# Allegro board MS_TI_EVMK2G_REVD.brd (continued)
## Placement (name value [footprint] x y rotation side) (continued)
C628  0.1uF  [CAP0201]  174.02 116.19 135 bottom
C630  0.1uF  [CAP0402]  193.04 96.53 0 bottom
C631  0.1uF  [CAP0201]  177.32 113.71 315 bottom
C632  1uF  [CAP0402]  149.73 97.8 180 bottom
C633  0.01uF  [CAP0402]  65.99 54.88 270 bottom
C634  0.1uF  [CAP0402]  193.34 26.86 90 bottom
C635  0.1uF  [CAP0402]  149.86 94.88 0 bottom
C637  0.1uF  [CAP0402]  142.88 92.6 0 bottom
C638  0.1uF  [CAP0402]  78.31 50.56 90 bottom
C639  0.1uF  [CAP0402]  140.46 97.42 270 bottom
C641  0.1uF  [CAP0402]  146.56 96.66 180 bottom
C642  0.1uF  [CAP0402]  140.59 88.66 0 bottom
C643  0.1uF  [CAP0402]  146.43 88.41 270 bottom
C645  0.1uF  [CAP0402]  194.26 149.52 0 bottom
C646  0.1uF  [CAP0402]  139.7 85.61 90 bottom
C647  0.1uF  [CAP0402]  144.53 85.99 180 bottom
C648  1uF  [CAP0402]  170.59 87.09 90 bottom
C649  0.01uF  [CAP0402]  172.95 89.35 180 bottom
C650  0.01uF  [CAP0402]  169.42 89.4 180 bottom
C651  0.01uF  [CAP0402]  285.33 57.56 180 bottom
C652  0.01uF  [CAP0201]  292.01 54.35 90 bottom
C653  0.01uF  [CAP0402]  173.48 87.77 180 bottom
C654  0.01uF  [CAP0402]  167.89 87.77 0 bottom
C655  0.1uF  [CAP0402]  196.47 79.14 0 bottom
C656  0.1uF  [CAP0402]  202.56 77.74 180 bottom
C657  0.1uF  [CAP0402]  188.98 76.47 90 bottom
C659  1uF  [CAP0402]  196.47 80.66 180 bottom
C661  0.1uF  [CAP0402]  44.32 114.95 270 bottom
C663  0.1uF  [CAP0402]  44.07 110.63 90 bottom
C665  0.1uF  [CAP0402]  100.71 93.99 180 bottom
C666  1uF  [CAP0402]  100.71 92.47 180 bottom
C667  0.1uF  [CAP0402]  117.86 127.4 270 top
C668  0.1uF  [CAP0402]  119.38 127.4 270 top
C669  0.1uF  [CAP0402]  120.9 127.4 270 top
C670  0.1uF  [CAP0402]  108.2 91.07 270 bottom
C671  0.01uF  [CAP0402]  11.94 43.58 270 bottom
C672  0.1uF  [CAP0402]  181.91 45.48 90 bottom
C673  0.01uF  [CAP0402]  181.53 39.89 180 bottom
C674  0.1uF  [CAP0402]  276.61 47.26 90 bottom
C675  0.1uF  [CAP0402]  37.77 129.99 0 bottom
C676  0.1uF  [CAP0402]  114.5 52.49 270 bottom
C677  10uF  [CAP0805]  121.03 109.36 270 top
C678  0.1uF  [CAP0402]  119.25 109.11 270 top
C679  0.1uF  [CAP0402]  281.94 43.96 0 bottom
C680  0.1uF  [CAP0402]  38.28 127.57 90 bottom
C681  0.01uF  [CAP0402]  36.6 203.8 90 top
C683  0.1uF  [CAP0402]  96.85 39.74 0 bottom
C684  0.1uF  [CAP0402]  96.85 36.57 0 bottom
C685  0.1uF  [CAP0402]  169.6 50.43 270 bottom
C686  0.01uF  [CAP0402]  170.26 52.47 0 bottom
C687  0.1uF  [CAP0402]  270.26 36.97 90 bottom
C688  0.1uF  [CAP0402]  38.28 124.53 270 bottom
C689  0.1uF  [CAP0402]  99.57 42.1 270 bottom
C690  0.1uF  [CAP0402]  30.53 123.89 90 bottom
C691  0.1uF  [CAP0402]  271.91 36.97 90 bottom
C692  0.1uF  [CAP0402]  286.38 39 90 bottom
C693  0.1uF  [CAP0402]  101.3 42.15 270 bottom
C694  0.1uF  [CAP0402]  102.31 33.52 90 bottom
C695  0.1uF  [CAP0402]  279.02 36.21 0 bottom
C696  0.1uF  [CAP0402]  275.59 36.21 0 bottom
C697  1uF  [CAP0402]  103.07 51.81 270 bottom
C698  0.1uF  [CAP0402]  103.07 42.15 270 bottom
C699  1uF  [CAP0402]  104.6 51.81 270 bottom
C700  0.1uF  [CAP0402]  105.11 37.2 180 bottom
C701  0.1uF  [CAP0402]  96.6 31.74 180 bottom
C702  10uF  [CAP0805]  275.34 31.89 90 bottom
C703  0.1uF  [CAP0402]  129.62 27.42 90 bottom
C704  0.01uF  [CAP0402]  85.51 28.95 270 bottom
C706  0.01uF  [CAP0402]  91.98 20.06 270 bottom
C707  0.01uF  [CAP0402]  84.87 20.56 90 bottom
C708  0.1uF  [CAP0402]  124.28 18.66 270 bottom
C709  10uF  [CAP0805]  124.66 13.71 90 bottom
C710  0.01uF  [CAP0402]  157.91 150.18 270 top
C711  4.7uF  [CAP0603]  273.43 151.53 0 bottom
C712  0.1uF  [CAP0402]  279.53 151.91 270 bottom
C713  4.7uF  [CAP0603]  256.79 151.02 0 bottom
C714  0.1uF  [CAP0402]  278 151.91 270 bottom
C715  0.1uF  [CAP0402]  262.89 152.03 270 bottom
C716  0.1uF  [CAP0402]  261.37 152.03 270 bottom
C717  4.7uF  [CAP0603]  242.82 150 0 bottom
C718  0.1uF  [CAP0402]  248.67 151.02 270 bottom
C719  0.1uF  [CAP0402]  247.14 151.02 270 bottom
C720  4.7uF  [CAP0603]  243.2 141.24 0 bottom
C721  0.1uF  [CAP0402]  248.79 142.51 270 bottom
C722  0.1uF  [CAP0402]  247.27 142.51 270 bottom
C723  4.7uF  [CAP0603]  255.19 140.78 180 bottom
C724  0.1uF  [CAP0402]  267.97 141.24 270 bottom
C725  0.1uF  [CAP0402]  266.45 141.24 270 bottom
C726  0.1uF  [CAP0402]  116.46 200.17 90 bottom
C733  0.1uF  [CAP0402]  293.73 52.64 180 bottom
C734  0.1uF  [CAP0402]  34.11 61.41 0 bottom
C735  22uF  [CAP0805]  93.85 46.7 270 top
C737  10uF  [CAP1210]  243.99 228.74 0 top
C738  10uF  [CAP1210]  243.99 232.42 0 top
C739  10uF  [CAP1210]  243.99 236.11 0 top
C740  0.1uF  [CAP0402]  243.79 237.33 0 bottom
C741  1uF  [CAP0402]  239.09 241.65 90 top
C742  3300pF  [CAP0805]  237.57 244.95 90 top
C743  0.1uF  [CAP0402]  239.34 233.39 180 top
C744  22uF  [CAP1210]  229.95 233.75 0 top
C745  22uF  [CAP1210]  229.95 233.75 0 bottom
C746  0.1uF  [CAP0402]  230.07 236.54 0 bottom
C749  0.1uF  [CAP0402]  294.31 233.67 180 bottom
C750  10uF  [CAP0805]  294.18 236.34 180 top
C752  3.3uF  [CAP0603]  35.56 186.5 90 bottom
C753  0.1uF  [CAP0402]  37.06 180.05 180 bottom
C754  3.3uF  [CAP0603]  28.91 150.61 90 bottom
C755  0.1uF  [CAP0402]  34.24 141.47 180 bottom
C756  0.01uF  [CAP0402]  126.9 103.06 0 top
C757  0.01uF  [CAP0402]  135 102.1 270 top
C758  1uF  [CAP0402]  134.04 107.03 180 top
C759  0.1uF  [CAP0402]  129.41 106.31 90 top
C760  0.1uF  [CAP0201]  155.93 107.08 270 bottom
C761  0.1uF  [CAP0402]  209.04 181.24 0 bottom
C762  0.1uF  [CAP0402]  193.04 221.93 90 top
C763  0.1uF  [CAP0402]  193.04 210.12 90 top
C775  0.01uF  [CAP0402]  130.73 33.29 0 bottom
C776  0.01uF  [CAP0402]  224.54 246.6 180 bottom
C777  0.1uF  [CAP0402]  157.1 95.14 0 top
C778  1uF  [CAP0402]  157.1 96.66 0 top
C780  0.1uF  [CAP0402]  215.26 89.17 0 top
C781  0.1uF  [CAP0402]  215.26 90.69 0 top
C782  0.1uF  [CAP0402]  232 94.71 0 top
C783  0.1uF  [CAP0402]  231.47 110.81 180 top
C784  0.1uF  [CAP0402]  191.13 141.87 180 top
C785  0.01uF  [CAP0402]  205.06 147.43 0 top
C786  0.01uF  [CAP0402]  208.24 147.43 180 top
C789  0.1uF  [CAP0402]  194.88 152.53 90 bottom
C790  0.01uF  [CAP0402]  208.98 153.08 180 bottom
C791  0.01uF  [CAP0402]  205.8 153.08 180 bottom
C792  0.1uF  [CAP0402]  41.66 107.33 90 top
C793  0.01uF  [CAP0201]  123.44 224.55 180 top
C794  1uF  [CAP0402]  202.95 135.02 0 top
C795  3.3uF  [CAP0402]  202.95 133.36 0 top
C796  4.7uF  [CAP0603]  202.82 133.36 0 bottom
C797  0.33uF  [CAP0201]  202.95 135.02 0 bottom
C798  0.01uF  [CAP0402]  108.84 194.58 90 top
C799  0.01uF  [CAP0402]  100.71 237.63 270 top
C800  0.01uF  [CAP0402]  295.15 66.31 0 top
C801  10uF  [CAP1210]  293.98 197.96 0 top
C802  10uF  [CAP1210]  293.9 194.22 0 top
C803  10uF  [CAP1210]  289.48 192.75 270 top
C804  0.1uF  [CAP0402]  290.17 199.51 90 top
C805  0.1uF  [CAP0402]  285.83 195.04 180 top
C806  15pF  [CAP0402]  287.43 202.96 90 top
C807  22uF  [CAP1210]  276.83 195.54 0 top
C808  22uF  [CAP1210]  271.5 195.57 180 top
C809  0.1uF  [CAP0402]  277.27 198.24 0 top
C810  1uF  [CAP0402]  285.93 204.84 90 top
C811  3300pF  [CAP0805]  281.48 204.43 180 top
C812  0.01uF  [CAP0402]  206.04 212.35 0 top
C813  0.01uF  [CAP0402]  216.99 211.75 270 top
C815  0.01uF  [CAP0402]  161.77 219.34 0 top
C816  0.1uF  [CAP0402]  37.11 208.24 0 top
C817  0.1uF  [CAP0402]  37.11 206.72 0 top
C818  0.1uF  [CAP0402]  44.48 212.69 90 top
C819  0.1uF  [CAP0402]  46 212.69 90 top
C820  0.1uF  [CAP0402]  28.96 92.98 180 top
C821  0.1uF  [CAP0402]  24.64 95.77 90 top
C822  0.1uF  [CAP0402]  28.96 94.5 180 top
C824  0.1uF  [CAP0603]  274.45 212.1 180 bottom
C825  22uF_100V  [CAPAE_GCASE]  270.05 227.8 0 top
C826  0.1uF  [CAP0603]  282.57 215.91 0 bottom
C827  0.01uF  [CAP0402]  279.02 215.91 180 bottom
D2  TLV431ACDBVR  [SOT23-5]  288.52 105.15 270 top
D3  B540C-13-F  [DIO_SMC]  268.22 237.12 180 top
D4  MMSD103T1G  [DIO_SOD123]  164.52 55.39 0 top
D5  B240A-13-F  [DIO_SMA]  136.91 228.11 180 bottom
D6  TPD1E10B06DPY  [DIO_DFN0402]  125.98 237.89 270 top
D7  TPD1E10B06DPY  [DIO_DFN0402]  108.27 238.01 270 top
D8  TPD1E10B06DPY  [DIO_DFN0402]  116.77 238.01 270 top
D9  TPD1E10B06DPY  [DIO_DFN0402]  98.99 238.27 270 top
D10  TPD1E10B06DPY  [DIO_DFN0402]  90.87 238.01 270 top
D11  TPD1E10B06DPY  [DIO_DFN0402]  82.61 238.14 270 top
D12  TPD1E10B06DPY  [DIO_DFN0402]  270.13 170.32 90 top
D13  TPD1E10B06DPY  [DIO_DFN0402]  282.12 170.32 90 top
D14  TPD2EUSB30DRTR  [SOT-3]  194.18 13.86 90 top
D15  TPD2EUSB30DRTR  [SOT-3]  215.77 24.53 90 top
D17  SMCJ64CA  [DIO_SMC]  257.81 236.49 180 top
D18  BZT52C13S  [DIO_SOD323]  249.05 226.2 180 top
D19  S1G-13-F  [DIO_SMA]  248.92 240.93 270 top
F2  5A  [FUSE_1206]  259.66 246.24 270 top
FB1  300E  [IND0603]  263.12 13.05 270 bottom
FB2  120E  [IND0402]  198.63 247.16 0 top
FB3  220E  [IND0603]  256.31 18.18 90 top
FB5  120E  [IND0402]  202.56 227.73 90 top
FB6  220E  [IND0603]  231.39 52.08 90 bottom
FB7  120E  [IND0402]  178.16 217.52 270 top
FB8  120E  [IND0402]  168.33 227.24 270 top
FB9  120E  [IND0402]  168.33 227.24 270 bottom
FB11  10E  [IND_201209_90X60_SMD]  152.15 48.33 90 top
FB13  120E  [IND0402]  265.56 173.88 90 top
FB14  120E  [IND0402]  229.49 85.36 90 top
FB15  120E  [IND0402]  226.44 160.29 90 top
FB17  120E  [IND0402]  174.32 137.53 270 bottom
FB19  120E  [IND0402]  182.07 138.9 270 bottom
FB20  120E  [IND0402]  157.71 139.11 180 bottom
FB21  120E  [IND0402]  182.63 143.96 270 bottom
FB22  120E  [IND0402]  187.25 144.34 270 bottom
FB23  120E  [IND0402]  189.28 126.23 90 bottom
FB24  120E  [IND0402]  189.23 122.75 270 bottom
FB25  120E  [IND0402]  192.2 119.5 180 bottom
FB26  1K  [EMIFIL_BLM15H_0402]  145.67 99.33 0 top
FB27  120E  [IND0402]  167.64 102.25 180 top
FB28  120E  [IND0402]  173.53 102.22 0 bottom
FB29  120E  [IND0402]  170.87 101.84 90 bottom
FB30  120E  [IND0402]  184.02 96.61 90 bottom
FB31  1K  [EMIFIL_BLM15H_0402]  149.73 96.66 0 top
FB32  120E  [IND0402]  76.91 54.11 270 top
FB33  120E  [IND0402]  6.98 68.98 180 top
FB34  120E  [IND0402]  14.12 130.09 90 bottom
FB35  300E  [IND0603]  90.25 44.44 180 top
FB36  10E  [IND_201209_90X60_SMD]  166.37 47.49 0 bottom
FB37  10E  [IND_201209_90X60_SMD]  176.02 45.15 90 bottom
FB38  300E  [IND0603]  110.54 31.23 0 top
FB39  300E  [IND0603]  95.78 46.7 90 top
FB40  10E  [IND_201209_90X60_SMD]  171.65 42.18 180 bottom
FB41  120E  [IND0402]  286.38 34.43 90 top
FB42  120E  [IND0402]  79.5 18.66 270 bottom
FB43  120E  [IND0402]  232.41 20.69 270 bottom
FB44  120E  [IND0402]  206.6 13.3 0 bottom
FB45  120E  [IND0402]  216.97 33.31 180 top
FB46  120E  [IND0402]  188.54 9.67 0 bottom
FB47  120E  [IND0402]  193.65 20.46 270 top
FB48  120E  [IND0402]  118.8 13.68 90 top
FB49  120E  [IND0402]  231.95 31.97 0 top
FB51  120E  [IND0402]  294.31 234.43 0 top
FB52  120E  [IND0402]  294.06 141.96 0 top
FB53  120E  [IND0402]  294.59 243.61 0 top
FL1  120E  [EMIFIL_BLM18R_0603]  249.94 247.66 180 top
FL2  120E  [EMIFIL_BLM18R_0603]  205.49 218.58 0 top
FL3  0.47uF  [EMIFIL_NFM18PS_0603]  253.14 46.34 180 top
FL5  0.47uF  [EMIFIL_NFM18PS_0603]  253.21 42.48 180 top
FL6  120E  [EMIFIL_BLM18R_0603]  293.5 156.86 0 top
FL7  670pF  [EMIFIL_NFL21SP_0805]  117.98 95.62 90 top
FL8  670pF  [EMIFIL_NFL21SP_0805]  99.31 97.42 180 top
FL9  670pF  [EMIFIL_NFL21SP_0805]  113.39 91.35 180 top
FL11  120E  [EMIFIL_BLM18R_0603]  117.02 13.17 90 top
FL13  50E  [EMIFIL_BLM31P_1206]  245.41 35.17 90 top
FL14  50E  [EMIFIL_BLM31P_1206]  259.69 45.28 90 top
FL15  50E  [EMIFIL_BLM31P_1206]  250.42 34.23 90 top
FL16  50E  [EMIFIL_BLM31P_1206]  247.88 34.23 90 top
FL19  120E  [EMIFIL_BLM18K_0603]  202.51 233.36 0 top
J1  CON_MUSB-B_5_F  [CON_USBB5_54819-0511_S_R_T]  256.57 13.86 0 top
J2  CON_EDGE_50X2  [CON_ED50X2_MEC6-150_S_R_S]  177.67 244.49 180 top
J3  CON_PWRJACK3_RAPC722  [CON_PWRJACK3_RAPC722_P_R_T]  282.96 237.15 180 top
J4  HDR_6X1  [HDR_6X1_100_S_T]  254.53 82.59 0 top
J5  CON36_PCI  [CON_PCI_18X2_10061913_S_S_S]  212.72 230.52 270 top
J6  HDR_1X4  [HDR_1X4_100_640454-4_S_T]  15.21 232.86 270 top
J7  HDR_7X2  [HDR_7X2_100_S_T]  104.17 217.97 90 top
J8  CON_10X2  [CON_10X2_FTR-110-51-S-D_P_S_S]  269.11 76.01 0 top
J9  HDR_3X1  [HDR_3X1_100_S_T]  93.09 197.12 90 top
J10  HDR_2X1  [HDR_2X1_100_S_T]  61.85 188.48 270 top
J11  HDR_3X1  [HDR_3X1_100_S_T]  103.38 189.75 0 top
J12  HDR_2X25  [HDR_2X25_100_S_T]  299.95 236.97 270 top
J13  HDR_2X1  [HDR_2X1_100_S_T]  235.71 153.18 0 top
J14  HDR_2X1  [HDR_2X1_100_S_T]  212.04 26.74 0 top
J15  HDR_3X1  [HDR_3X1_100_S_T]  64.36 157.01 0 top
J16  HDR_3X1  [HDR_3X1_100_S_T]  74.88 157.11 0 top
J17  HDR_3X1  [HDR_3X1_100_S_T]  271.02 178.45 0 top
J18  HDR_5X1  [HDR_5X1_100_S_T]  273.94 123.71 0 top
J19  CON_PMC_30X2_F  [CON_PMC30X2_HQCD-030_S_S_S]  217.93 77.61 180 top
J21  CON_FLEX_1X6_68610614122  [CON_FLEX_6X1_68610_S_R_S]  68.53 50.65 0 top
J22  CON_FLEX_1X40_62684-4011  [CON_FLEX40X1_62684-40_S_R_S]  44.39 58.65 180 top
J23  CON_MUSB-B_5_F  [CON_USBAB5_54819-0572_S_R_S]  3.2 61.1 0 top
J25  HDR_2X1  [HDR_2X1_100_S_T]  44.3 162.88 90 top
J26  HDR_2X1  [HDR_2X1_100_S_T]  39.12 198.34 90 top
J27  HDR_2X1  [HDR_2X1_100_S_T]  134.06 29.71 180 top
J28  HDR_2X1  [HDR_2X1_100_S_T]  139.52 29.71 180 top
J29  HDR_2X1  [HDR_2X1_100_S_T]  144.86 29.71 180 top
J30  HDR_2X1  [HDR_2X1_100_S_T]  191.97 16.5 0 top
J31  CON_RJ45-14_LPJG16314A4NL  [CON_RJ45-14_LPJG16314A4NL_S_R_T]  164.01 26.81 0 top
J32  CON_AUDIOJACK4_SJ-3524-SMT  [CON_AV4_SJ-3524-SMT-1_R_S]  275.08 15.51 90 top
J33  CON_AUDIOJACK4_SJ-3524-SMT  [CON_AV4_SJ-3524-SMT-1_R_S]  288.42 15.51 90 top
J34  CON_PMC_20X2_F  [CON_PMC20X2_QSH-D-DP_S_S_S]  131.52 15.86 180 top
J35  CON_USB-A_87583-2010BLF  [CON_USBA4_87583-2010_S_R_S]  215.81 13.95 0 top
J36  CON_HDMI_19X1  [CON_19X1_10029449-001RLF_S_R_S]  86.69 11.72 0 top
J37  CON_SDCARD_8_DM3AT-SF-PEJM5  [CON_SD_8_DM3AT-SF-PEJM_S_R_S]  239.19 15.98 0 top
J38  CON_USB-AB_5_M  [CON_USBAB5_ZX62_P_R_S]  194.48 8.68 0 top
J39  HDR_2X1  [HDR_2X1_100_S_T]  275.21 156.48 0 top
J40  HDR_2X1  [HDR_2X1_100_S_T]  258.19 154.7 0 top
J41  HDR_2X1  [HDR_2X1_100_S_T]  242.57 154.95 0 top
J42  HDR_2X1  [HDR_2X1_100_S_T]  244.98 144.03 0 top
J43  HDR_2X1  [HDR_2X1_100_S_T]  256.54 144.54 0 top
J44  HDR_3X1  [HDR_3X1_100_S_T]  231.14 248.05 90 top
J45  HDR_3X1  [HDR_3X1_100_S_T]  287.91 69.86 90 top
J46  HDR_3X1  [HDR_3X1_100_S_T]  260.99 227.6 0 top
J48  HDR_3X1  [HDR_3X1_100_S_T]  150.95 29.71 180 top
J49  HDR_6X1  [HDR_6X1_100_S_T]  44.55 100.07 0 top
J50  HDR_2X1  [HDR_2X1_100_S_T]  293.62 229.12 0 top
JP1  HDR_2X50  [HDR_2X50_100_S_T]  299.97 143.68 270 top
L1  22uH  [IND_DR1040_415X405_SMD]  141.1 223.92 0 top
L2  2.2uH  [IND1008]  276.83 98.92 90 top
L3  3.3uH  [IND_PCMB104T_455X405_SMD]  254.76 209.44 180 top
L4  2.7uH  [IND_XAL7030_315X315_SMD]  254.25 190.64 0 top
L5  2.2uH  [IND_VLCF5020T_205X210_SMD]  234.06 181.12 0 top
L6  2.2uH  [IND_VLCF5020T_205X210_SMD]  254.76 168.29 270 top
L7  2.2uH  [IND_VLCF5020T_205X210_SMD]  233.81 166.26 180 top
L8  4.7uH  [IND_VLCF5020T_205X210_SMD]  48.97 75.76 180 top
L9  2.2uH  [IND_B82476A_510X370_SMD]  233.53 226.91 180 top
L10  2.2uH  [IND_B82476A_510X370_SMD]  280.31 188.58 180 top
L11  47nH  [FILTRER_COILCRAFT_0805]  197.87 18.43 180 top
L12  47nH  [FILTRER_COILCRAFT_0805]  215.77 27.45 270 top
LD1  598-8140-107F  [LED_0805]  69.75 138.36 90 top
LD2  598-8140-107F  [LED_0805]  77.5 138.36 90 top
LD3  598-8140-107F  [LED_0805]  65.94 138.36 90 top
LD4  598-8140-107F  [LED_0805]  73.69 138.36 90 top
LD5  598-8140-107F  [LED_0805]  80.8 138.36 90 top
LD6  598-8170-107F  [LED_0805]  261.49 22.11 270 top
LD7  598-8170-107F  [LED_0805]  257.56 22.24 270 top
LD8  598-8170-107F  [LED_0805]  253.36 22.37 270 top
LD9  598-8170-107F  [LED_0805]  253.94 246.01 0 top
LD10  598-8170-107F  [LED_0805]  61.75 138.36 90 top
LD11  598-8191-107F  [LED_0805]  24.38 247.16 90 top
LD12  598-8170-107F  [LED_0805]  28.83 247.16 90 top
LD13  598-8191-107F  [LED_0805]  57.68 138.36 90 top
LD14  598-8110-107F  [LED_0805]  253.94 241.19 0 top
LD15  598-8110-107F  [LED_0805]  253.56 243.6 180 top
MOD1  NHD-C12832A1Z-NSW-BBW-3V3  [MOD17_NHD-C12832A1Z]  42.93 224 0 top
NOREF  -  [unnamed]  8.26 17.16 0 top
NOREF#2  -  [#2]  149.92 161.69 0 top
NOREF#3  -  [#2]  94.11 -165.34 0 top
NOREF#4  -  [#2]  140.59 20.72 0 top
NOREF#5  -  [unnamed#3]  5.71 135.78 180 top
NOREF#6  -  [#2]  149.92 166.26 0 top
NOREF#7  -  [#2]  0.64 251.09 0 top
NOREF#8  -  [unnamed#3]  110.87 11.46 0 top
NOREF#9  -  [unnamed]  12.78 33.34 0 top
NOREF#10  -  [unnamed#3]  300.55 245.92 0 top
NOREF#11  -  [#2]  0.64 258 0 top
NOREF#12  -  [unnamed]  8.26 238.14 0 top
NOREF#13  -  [unnamed]  295.27 17.16 0 top
NOREF#14  -  [unnamed#3]  111.6 135.78 0 top
NOREF#15  -  [unnamed]  10.95 254.37 0 top
NOREF#16  -  [#2]  -211.46 -64.95 0 top
NOREF#17  -  [#2]  305.63 0 90 top
NOREF#18  -  [unnamed]  5.82 3.24 0 top
NOREF#19  -  [unnamed#3]  300.55 166.92 180 top
NOREF#20  -  [unnamed#3]  300.55 11.46 0 top
NOREF#21  -  [#2]  40.51 -47.36 0 top
NOREF#22  -  [#2]  305.63 7 90 top
NOREF#23  -  [#2]  41.2 218.1 0 top
NOREF#24  -  [unnamed]  12.78 84.14 0 top
NOREF#25  -  [unnamed]  123.98 84.11 0 top
NOREF#26  -  [unnamed]  10.95 3.37 0 top
NOREF#27  -  [unnamed#3]  5.71 245.92 0 top
NOREF#28  -  [unnamed#3]  134.82 245.92 0 top
NOREF#29  -  [unnamed#3]  261.6 135.78 0 top
NOREF#30  -  [#2]  0.64 6.79 0 top
NOREF#31  -  [unnamed]  296.04 254.37 0 top
NOREF#32  -  [unnamed]  5.82 254.27 0 top
NOREF#33  -  [unnamed#3]  5.71 11.46 0 top
NOREF#34  -  [#2]  -224.16 -63.92 0 top
NOREF#35  -  [unnamed]  123.9 33.34 0 top
NOREF#36  -  [unnamed]  300.1 254.27 0 top
NOREF#37  -  [unnamed#3]  300.55 151.92 180 top
NOREF#38  -  [unnamed#3]  152.17 11.46 0 top
NOREF#39  -  [unnamed]  10.95 254.37 180 bottom
NOREF#40  -  [#2]  117.04 73.14 180 bottom
NOREF#41  -  [unnamed]  296.04 254.37 180 bottom
NOREF#42  -  [unnamed]  295.27 17.16 180 bottom
NOREF#43  -  [unnamed]  8.26 17.16 180 bottom
NOREF#44  -  [unnamed]  10.95 3.37 180 bottom
NOREF#45  -  [unnamed]  8.26 238.14 180 bottom
P1  CON_DSUB_9_M  [CON_DB9_182-009-113R531_P_R_T]  11.68 119.52 270 top
P2  CON_DSUB_9_M  [CON_DB9_182-009-113R531_P_R_T]  11.68 205.32 270 top
P3  CON_DSUB_9_M  [CON_DB9_182-009-113R531_P_R_T]  11.68 162.52 270 top
Q6  BSS138  [TO_SOT23-123]  257.56 26.86 180 top
Q7  BSS138  [TO_SOT23-123]  253.36 26.94 180 top
Q8  BSS138  [TO_SOT23-123]  61.87 133.44 0 top
Q9  BSS138  [TO_SOT23-123]  24.26 242.33 0 top
Q10  BSS138  [TO_SOT23-123]  28.83 242.33 0 top
Q11  BSS138  [TO_SOT23-123]  57.68 133.44 0 top
Q12  BSS138  [TO_SOT23-123]  39.83 81.22 0 top
Q13  FDT434P  [SOT223-3]  156.9 45.99 180 top
Q14  BSS138  [TO_SOT23-123]  69.75 133.7 0 top
Q15  BSS138  [TO_SOT23-123]  65.94 133.7 0 top
Q19  BSS138  [TO_SOT23-123]  249.3 229.63 0 top
Q20  SUM60N10-17-E3  [D2PAK-3]  283.77 226.38 0 top
R1  4.7K_5%  [RES0402]  89.69 116.12 270 top
R2  4.7K_5%  [RES0402]  91.21 116.12 90 bottom
R3  4.7K_5%  [RES0402]  96.79 116.12 270 top
R4  4.7K_5%  [RES0402]  96.79 116.12 90 bottom
R5  10K_1%  [RES0402]  94.62 179.21 180 top
R11  10K_1%  [RES0402]  92.74 116.12 90 top
R12  68E  [RES0402]  69.75 138.46 90 bottom
R13  68E  [RES0402]  65.94 138.33 90 bottom
R14  68E  [RES0402]  80.8 138.5 90 bottom
R15  68E  [RES0402]  73.69 138.5 90 bottom
R16  68E  [RES0402]  77.5 138.5 90 bottom
R17  0E_1%  [RES0402]  149.73 80.53 0 top
R18  0E_1%  [RES0402]  149.73 82.06 0 top
R19  0E_1%  [RES0402]  153.54 83.74 0 top
R20  0E_1%  [RES0402]  153.54 82.18 0 top
R21  0E_1%  [RES0402]  150.37 85.87 0 top
R22  0E_1%  [RES0402]  150.37 84.38 0 top
R23  0E_1%  [RES0402]  150.62 89.3 0 top
R24  0E_1%  [RES0402]  150.62 90.82 0 top
R30  1K  [RES0402]  256.92 247.03 270 top
R31  470E  [RES0402]  259.59 21.81 90 top
R32  470E  [RES0402]  255.52 21.94 90 top
R33  470E  [RES0402]  251.46 22.07 90 top
R34  0E_1%  [RES0402]  264.44 13.48 270 top
R35  V5.5MLA0603H  [VAR0603]  259.87 18.18 270 top
R36  2.2K_1%  [RES0402]  257.51 29.86 180 top
R37  2.2K_1%  [RES0402]  253.36 29.86 180 top
R38  10K_1%  [RES0402]  220.98 237.38 180 top
R39  0E_1%  [RES0402]  60.86 129.5 270 top
R40  10K_1%  [RES0402]  23.37 238.52 90 top
R41  0E_1%  [RES0402]  28.07 238.52 270 top
R42  0E_1%  [RES0402]  56.79 129.63 270 top
R43  10K_1%  [RES0402]  220.98 235.47 180 top
R44  100K  [RES0402]  285.6 91.94 0 top
R45  1K  [RES0402]  250.44 86.5 90 top
R46  2.2K_1%  [RES0402]  248.72 86.45 90 top
R47  2.94K_1%  [RES0402]  284.07 100.95 270 top
R48  0E_1%  [RES0402]  176.66 236.23 270 top
R49  0E_1%  [RES0402]  178.18 236.23 270 top
R50  0E_1%  [RES0402]  179.7 236.23 270 top
R51  0E_1%  [RES0402]  181.23 236.23 270 top
R52  10K_1%  [RES0402]  182.88 236.23 90 top
R53  10K_1%  [RES0402]  184.4 236.23 90 top
R54  10K_1%  [RES0402]  185.93 236.23 90 top
R55  10K_1%  [RES0402]  187.45 236.23 90 top
R56  10K_1%  [RES0402]  188.98 236.23 90 top
R57  10K_1%  [RES0402]  190.5 236.23 90 top
R58  10K_1%  [RES0402]  192.02 236.23 90 top
R59  0E_1%  [RES0402]  195.2 236.23 270 top
R60  0E_1%  [RES0402]  169.04 235.98 270 top
R61  0E_1%  [RES0402]  170.56 235.98 270 top
R62  0E_1%  [RES0402]  172.08 235.98 270 top
R63  0E_1%  [RES0402]  173.61 235.98 270 top
R64  10K_1%  [RES0402]  282.55 100.95 90 top
R65  0E_1%  [RES0402]  219.79 242.36 0 top
R66  10K_1%  [RES0402]  219.79 244.26 0 top
R67  10K_1%  [RES0402]  280.25 100.32 180 top
R68  100K  [RES0402]  280.01 92.06 270 top
R69  0E  [RES0402]  198.25 232.42 180 top
R71  1K_1%  [RES0603]  128.02 230.77 270 top
R72  10K_1%  [RES0402]  259.46 97.3 270 top
R73  30.1K _1%  [RES0402]  198.37 230.39 0 top
R75  10K_1%  [RES0402]  276.45 93.59 0 top
R76  2.94K_1%  [RES0402]  276.45 92.06 0 top
R77  47E_1%  [RES0402]  255.4 98.06 0 top
R78  1K  [RES0402]  255.4 96.41 0 top
R79  1K  [RES0402]  255.4 93.36 0 top
R80  47E_1%  [RES0402]  255.14 103.27 0 top
R81  47E_1%  [RES0402]  228.47 95.39 270 top
R82  57.6K_1%  [RES0402]  193.93 228.74 0 bottom
R83  0E  [RES0402]  273.53 99.56 0 top
R84  10.2K _1%  [RES0603]  273.41 95.37 270 top
R85  10K_1%  [RES0402]  268.58 63.57 180 top
R86  22E_1%  [RES0402]  239.27 66.11 270 top
R87  22E_1%  [RES0402]  237.62 66.11 270 bottom
R88  22E_1%  [RES0402]  240.79 66.11 270 top
R89  470E  [RES0402]  244.2 66.11 90 top
R90  470E  [RES0402]  240.66 66.11 90 bottom
R91  22E_1%  [RES0402]  242.19 66.11 270 bottom
R92  22E_1%  [RES0402]  247.24 66.11 270 top
R93  22E_1%  [RES0402]  248.77 66.11 270 top
R94  22E_1%  [RES0402]  250.29 66.11 270 top
R95  1K  [RES0402]  243.71 110.38 90 bottom
R96  2.2K_1%  [RES0402]  231.11 65.34 90 top
R97  2.2K_1%  [RES0402]  232.64 65.34 90 top
R98  2.2K_1%  [RES0402]  235.69 65.34 90 top
R99  2.2K_1%  [RES0402]  234.16 65.34 90 top
R100  220E  [RES0805]  37.97 230.85 270 bottom
R101  10K_1%  [RES0402]  254.99 64.84 0 top
R102  10K_1%  [RES0402]  254.99 63.31 180 top
R103  10K_1%  [RES0402]  28.07 232.81 90 top
R104  470E  [RES0402]  250.06 110.5 90 top
R105  10K_1%  [RES0402]  268.58 62.04 180 top
R106  0E  [RES0402]  37.72 234.41 0 bottom
R107  1K  [RES0402]  245.87 110.5 90 bottom
R108  1K  [RES0402]  248.03 110.5 90 bottom
R109  0E_1%  [RES0402]  120.14 229 90 top
R110  470E  [RES0402]  248.03 110.5 90 top
R111  10K_1%  [RES0402]  268.58 60.52 180 top
R112  0E  [RES0402]  41.66 234.54 180 bottom
R113  0E  [RES0402]  247.27 106.82 90 top
R114  470E  [RES0402]  245.87 110.5 90 top
R115  1K  [RES0402]  250.06 110.5 90 bottom
R116  470E  [RES0402]  227.94 58.69 180 top
R117  0E_1%  [RES0402]  66.93 218.2 90 top
R118  0E_1%  [RES0402]  68.45 218.2 90 top
R119  10K_1%  [RES0402]  263.25 58.23 0 top
R120  470E  [RES0402]  227.94 60.21 180 top
R121  470E  [RES0402]  243.71 110.38 90 top
R122  470E  [RES0402]  243.59 107.08 90 top
R123  10K_1%  [RES0402]  263.25 56.71 0 top
R124  470E  [RES0402]  227.94 57.09 180 top
R125  470E  [RES0402]  242.06 107.08 90 top
R126  47E_1%  [RES0402]  241.68 86.76 270 top
R127  47E_1%  [RES0402]  263.25 55.18 0 top
R128  470E  [RES0402]  227.94 55.56 180 top
R129  470E  [RES0402]  240.41 107.08 90 top
R130  47E_1%  [RES0402]  263.25 53.66 0 top
R131  10K_1%  [RES0402]  255.91 224.93 0 top
R132  4.7K_5%  [RES0402]  22.35 221.25 180 top
R133  22E_1%  [RES0402]  98.83 202.1 180 top
R134  4.7K_5%  [RES0402]  25.46 220.99 90 top
R135  4.7K_5%  [RES0402]  28.7 220.99 90 top
R136  47E_1%  [RES0402]  263.25 52.14 0 top
R138  10K_1%  [RES0402]  191.41 218.79 90 top
R139  10K_1%  [RES0402]  196.88 221.12 0 top
R140  1.69K_1%  [RES0402]  261.49 218.2 90 top
R141  22E_1%  [RES0402]  263.25 50.61 180 top
R142  1K  [RES0402]  272.29 78.75 90 bottom
R143  10K_1%  [RES0402]  226.92 49.98 180 top
R144  47E_1%  [RES0402]  235.58 101.49 180 top
R145  47E_1%  [RES0402]  232.41 98.44 180 top
R146  47E_1%  [RES0402]  232.41 96.79 180 top
R147  47E_1%  [RES0402]  235.58 96.15 180 top
R148  47E_1%  [RES0402]  235.58 94.63 180 top
R149  100E  [RES0402]  263.25 49.09 180 top
R150  10K_1%  [RES0402]  262 209.36 270 top
R152  1K  [RES0402]  226.92 46.93 0 top
R153  0E_1%  [RES0402]  80.65 205.12 270 top
R154  0E_1%  [RES0402]  82.17 205.12 270 top
R155  53.6K_1%  [RES0603]  264.8 218.33 270 top
R156  470E  [RES0402]  263.25 47.56 0 top
R157  100K  [RES0402]  264.92 209.56 90 top
R158  1.5K_5%  [RES0402]  255.88 46.12 90 top
R160  0E_1%  [RES0402]  70.99 204.48 90 bottom
R161  0E_1%  [RES0402]  72.52 204.48 90 bottom
R162  0E_1%  [RES0402]  69.98 205.37 90 top
R163  0E_1%  [RES0402]  77.93 204.99 90 bottom
R164  0E_1%  [RES0402]  76.61 204.92 90 bottom
R165  1K  [RES0402]  226.92 48.58 0 top
R166  0E_1%  [RES0402]  79.25 205.15 90 top
R167  0E_1%  [RES0402]  263.25 46.04 0 top
R168  10K_1%  [RES0402]  127.76 237.38 270 top
R169  10K_1%  [RES0402]  226.92 45.28 180 top
R170  0E_1%  [RES0402]  66.37 203.34 0 top
R171  2K_1%  [RES0402]  85.09 200.8 270 top
R172  1K  [RES0402]  226.92 43.5 180 top
R173  47E_1%  [RES0402]  227.97 54.04 180 top
R174  0E_1%  [RES0402]  77.6 205.12 90 top
R175  100E_5%  [RES0402]  91.9 229.45 0 top
R176  10K_1%  [RES0402]  78.18 234.15 0 top
R177  0E_1%  [RES0402]  66.37 204.76 0 top
R178  1K  [RES0402]  226.92 41.98 180 top
R179  100E  [RES0402]  96.65 199.02 180 top
R180  10K_1%  [RES0402]  82.8 198.9 0 top
R181  0E_1%  [RES0402]  219.58 221.76 180 top
R182  0E_1%  [RES0402]  219.58 223.28 180 top
R183  100E_5%  [RES0402]  91.9 230.98 0 top
R184  10K_1%  [RES0402]  78.18 232.63 0 top
R185  10K_1%  [RES0402]  246.1 40.2 90 top
R187  1K  [RES0402]  230.86 39.94 270 top
R188  10K_1%  [RES0402]  96.77 197.37 180 top
R189  47E_1%  [RES0402]  234.54 39.94 90 top
R190  100E_5%  [RES0402]  91.9 232.5 0 top
R191  10K_1%  [RES0402]  78.18 231.1 0 top
R192  100K  [RES0402]  64.14 195.54 0 top
R193  10K_1%  [RES0402]  88.47 194.71 0 top
R194  1K  [RES0402]  232.38 39.94 270 top
R195  0E_1%  [RES0402]  67.31 195.54 180 bottom
R196  10K_1%  [RES0402]  118.81 237.38 270 top
R197  100E_5%  [RES0402]  91.9 234.03 0 top
R198  10K_1%  [RES0402]  78.18 229.58 0 top
R199  10K_1%  [RES0402]  88.47 196.15 0 top
R200  0E_1%  [RES0402]  83.44 194.07 180 bottom
R202  10K_1%  [RES0402]  88.44 191.68 0 top
R203  0E_1%  [RES0402]  83.44 192.8 180 bottom
R204  10K_1%  [RES0402]  88.34 193.18 0 top
R205  22E_1%  [RES0402]  83.06 190.64 180 top
R206  39.2E_1%  [RES0402]  137.16 187.47 90 top
R207  39.2E_1%  [RES0402]  143.26 187.47 90 top
R208  39.2E_1%  [RES0402]  147.32 182.77 0 top
R209  39.2E_1%  [RES0402]  141.73 187.47 90 top
R210  39.2E_1%  [RES0402]  147.95 174 0 top
R211  39.2E_1%  [RES0402]  140.21 187.47 90 top
R212  39.2E_1%  [RES0402]  134.11 187.47 90 top
R213  39.2E_1%  [RES0402]  135.64 187.47 90 top
R214  39.2E_1%  [RES0402]  131.06 187.47 90 top
R215  39.2E_1%  [RES0402]  138.68 187.47 90 top
R216  39.2E_1%  [RES0402]  150.11 180.56 0 top
R217  39.2E_1%  [RES0402]  150.11 182.08 0 top
R218  10K_1%  [RES0402]  62.71 160.06 90 top
R219  10K_1%  [RES0402]  61.32 160.06 90 top
R220  0E_1%  [RES0402]  73.03 187.77 270 top
R221  0E_1%  [RES0402]  76.33 188.23 270 top
R222  0E_1%  [RES0402]  117.09 210.2 270 top
R223  0E_1%  [RES0402]  118.75 210.2 90 top
R224  10K_1%  [RES0402]  109.92 237.63 270 top
R225  10K_1%  [RES0402]  65.02 188.23 0 top
R226  4.87K_1%  [RES0402]  80.26 188.23 270 top
R227  0E_1%  [RES0402]  81.92 188.23 90 top
R228  10K_1%  [RES0402]  89.92 184.16 180 bottom
R229  10K_1%  [RES0402]  89.66 187.97 270 top
R230  39.2E_1%  [RES0402]  126.11 183.02 180 top
R231  0E_1%  [RES0402]  68.2 188.23 180 bottom
R232  0E_1%  [RES0402]  68.2 186.7 180 top
R233  39.2E_1%  [RES0402]  126.11 169.31 180 top
R236  10K_1%  [RES0402]  105.92 185.05 0 top
R237  39.2E_1%  [RES0402]  126.11 181.5 180 top
R238  10K_1%  [RES0402]  98.68 183.53 180 top
R239  10K_1%  [RES0402]  105.92 183.4 0 top
R240  0E_1%  [RES0402]  267.21 78.75 270 bottom
R241  39.2E_1%  [RES0402]  126.11 178.45 180 top
R242  10K_1%  [RES0402]  238.28 26.81 90 top
R243  0E_1%  [RES0402]  267.23 73.62 270 bottom
R244  39K_1%  [RES0603]  242.44 182.39 90 top
R245  0E_1%  [RES0402]  258.57 181.88 0 top
R247  39.2E_1%  [RES0402]  126.11 170.83 180 top
R248  10K_1%  [RES0402]  261.11 181.23 270 top
R249  10K_1%  [RES0402]  98.04 180.1 180 top
R251  10K_1%  [RES0402]  105.03 179.97 0 top
R252  10K_1%  [RES0402]  69.8 160.29 90 top
R253  10K_1%  [RES0402]  269.62 153.56 270 bottom
R254  10K_1%  [RES0402]  102.42 237.63 270 top
R255  10K_1%  [RES0402]  85.73 179.59 180 top
R256  39.2E_1%  [RES0402]  132.59 187.47 90 top
R257  0.0E  [RES0603]  271.02 98.82 270 top
R258  0E  [RES0402]  173.47 194.77 90 top
R259  10K_1%  [RES0402]  105.03 178.45 180 top
R260  10K_1%  [RES0402]  174.11 175.47 270 top
R261  39.2E_1%  [RES0402]  126.11 167.78 180 top
R262  10K_1%  [RES0402]  64.39 177.94 270 top
R263  10K_1%  [RES0402]  60.32 178.2 270 top
R264  10K_1%  [RES0402]  74.17 159.48 180 top
R265  0E_1%  [RES0402]  195.51 171.74 180 top
R266  10K_1%  [RES0402]  48.16 181.6 180 top
R267  0E_1%  [RES0402]  175.25 198.84 270 top
R268  10K_1%  [RES0402]  175.12 194.77 90 top
R269  10K_1%  [RES0402]  175.25 171.28 270 top
R270  0.0E  [RES0603]  227.05 40.32 0 top
R271  10K_1%  [RES0402]  175.63 175.47 270 top
R272  10K_1%  [RES0402]  84.96 176.67 270 top
R273  10K_1%  [RES0402]  86.49 176.67 90 top
R274  10K_1%  [RES0402]  88.01 176.67 90 top
R275  10K_1%  [RES0402]  89.54 176.67 90 top
R276  10K_1%  [RES0402]  91.06 176.67 90 top
R277  10K_1%  [RES0402]  92.58 176.67 90 top
R278  10K_1%  [RES0402]  94.11 176.67 90 top
R279  39.2E_1%  [RES0402]  126.11 184.55 180 top
R280  10K_1%  [RES0402]  68.96 175.4 180 top
R281  10K_1%  [RES0402]  176.9 171.28 270 top
R282  10K_1%  [RES0402]  43.31 178.2 180 top
R283  10K_1%  [RES0402]  55.88 178.2 270 top
R284  0E_1%  [RES0402]  251.76 174.03 180 top
R285  39.2E_1%  [RES0402]  126.11 176.93 180 top
R286  10K_1%  [RES0402]  182.62 175.47 270 top
R287  10K_1%  [RES0402]  178.43 194.77 270 top
R288  10K_1%  [RES0402]  95.38 173.88 0 top
R289  10K_1%  [RES0402]  92.52 237.5 270 top
R290  10K_1%  [RES0402]  68.96 173.75 180 top
R291  10K_1%  [RES0402]  43.31 176.67 180 top
R292  10K_1%  [RES0402]  178.81 171.28 270 top
R293  0.0E  [RES0603]  282.32 87.14 180 top
R294  10K_1%  [RES0402]  278.64 167.67 270 top
R295  39.2E_1%  [RES0402]  126.11 175.4 180 top
R296  0.0E  [RES0603]  252.7 33.97 270 top
R298  0E_1%  [RES0402]  251.74 172.51 180 top
R299  10K_1%  [RES0402]  179.19 175.47 270 top
R300  10K_1%  [RES0402]  95.38 172.35 0 top
R301  0E  [RES0402]  184.9 196.17 180 top
R302  10K_1%  [RES0402]  43.31 175.02 0 top
R304  10K_1%  [RES0402]  180.97 171.28 270 bottom
R305  39.2E_1%  [RES0402]  126.11 173.88 180 top
R306  39.2E_1%  [RES0402]  144.78 187.47 90 top
R307  39.2E_1%  [RES0402]  129.54 187.47 90 top
R308  39.2E_1%  [RES0402]  126.11 172.35 180 top
R309  39.2E_1%  [RES0402]  126.11 179.97 180 top
R310  10K_1%  [RES0402]  58.42 169.56 180 top
R311  0E_1%  [RES0402]  120.27 210.2 270 top
R312  10K_1%  [RES0402]  62.36 171.21 180 bottom
R313  10K_1%  [RES0402]  84.26 237.5 270 top
R314  100E  [RES0402]  213.36 85.23 270 top
R315  10K_1%  [RES0402]  207.32 167.42 0 top
R316  10K_1%  [RES0402]  88.01 165.62 270 top
R317  100E_5%  [RES0402]  227.84 85.36 90 top
R318  10K_1%  [RES0402]  195.51 170.21 180 top
R319  4.7K_5%  [RES0402]  231.5 105.58 180 top
R321  10K_1%  [RES0402]  207.32 170.47 180 top
R322  10E  [RES0402]  226.31 85.36 90 top
R323  22E_1%  [RES0402]  224.8 95.67 90 top
R324  0E_1%  [RES0402]  256.16 163.34 90 top
R325  0E_1%  [RES0402]  257.94 163.34 90 top
R326  4.7K_5%  [RES0402]  215.01 85.23 90 top
R327  10E  [RES0402]  224.79 85.36 90 top
R328  4.7K_5%  [RES0402]  184.89 137.56 0 top
R329  22E_1%  [RES0402]  223.27 85.36 90 top
R330  120K  [RES0603]  232.41 160.42 180 top
R333  100K  [RES0402]  207.62 186.15 180 top
R334  10K_1%  [RES0402]  280.16 167.67 270 top
R336  4.7K_5%  [RES0402]  219.68 108.24 270 top
R338  0E_1%  [RES0402]  252.09 159.02 180 top
R339  1K  [RES0402]  207.49 178.48 0 top
R340  0E_1%  [RES0402]  232.03 158.64 180 top
R341  0E_1%  [RES0402]  255.52 158.64 270 top
R342  0E_1%  [RES0402]  219.96 85.36 270 top
R343  4.7K_5%  [RES0402]  231.5 107.23 180 top
R344  100K  [RES0402]  193.78 189.19 0 top
R345  120K  [RES0603]  252.09 157.37 180 top
R346  120K  [RES0603]  232.03 156.86 180 top
R347  1K  [RES0402]  187.71 146.83 180 bottom
R348  4.7K_5%  [RES0402]  221.61 95.39 90 top
R349  0E  [RES0402]  230.76 80.15 270 top
R350  10E  [RES0402]  208.66 101.97 180 bottom
R351  4.7K_5%  [RES0402]  204.6 98.31 90 bottom
R352  10E  [RES0402]  208.76 99.79 180 bottom
R353  10K_1%  [RES0402]  228.22 103.27 90 top
R354  0E_1%  [RES0402]  220.83 103.29 0 top
R355  4.7K_5%  [RES0402]  206.25 98.44 90 bottom
R357  0.001E_1%  [RES2725]  263.65 151.65 90 top
R358  10E  [RES0402]  226.44 70.12 90 top
R359  0.1E_1%  [RES1210]  278.76 152.03 90 top
R360  0.05E_1%  [RES1812]  248.03 150.76 90 top
R362  10E  [RES0402]  230 90.95 270 bottom
R364  10E  [RES0402]  221.11 70.25 90 top
R365  0E_1%  [RES0402]  164.47 149.62 270 top
R366  0E_1%  [RES0402]  165.99 149.62 270 top
R368  1.2K_1%  [RES0603]  168.02 148.73 90 top
R369  1.2K_1%  [RES0603]  169.8 148.73 90 top
R370  0E_1%  [RES0402]  271.65 146.06 270 top
R371  4.7K_5%  [RES0402]  276.48 146.06 270 top
R373  0E_1%  [RES0402]  175.89 144.54 270 top
R374  0E_1%  [RES0402]  274.19 145.43 0 top
R376  4.7K_5%  [RES0402]  162.18 144.41 90 top
R377  4.7K_5%  [RES0402]  163.7 144.41 90 top
R378  10K_1%  [RES0402]  165.23 144.41 270 top
R379  10K_1%  [RES0402]  166.75 144.41 270 top
R381  0.1E_1%  [RES1210]  248.16 142.25 90 top
R383  0.05E_1%  [RES1812]  267.67 142.48 90 top
R385  240E_1%  [RES0201]  161.72 149.62 270 top
R386  240E_1%  [RES0201]  162.56 149.62 270 top
R387  0E_1%  [RES0402]  177.93 138.95 270 top
R388  0E_1%  [RES0402]  179.2 138.95 270 top
R391  4.7K_5%  [RES0402]  211.2 70.25 270 top
R393  0E_1%  [RES0402]  197.23 137.17 180 bottom
R394  0E_1%  [RES0402]  192.15 130.16 180 top
R396  0E_1%  [RES0402]  197.23 132.86 180 top
R398  0E_1%  [RES0402]  192.2 131.59 180 top
R401  0E_1%  [RES0402]  192.2 134.63 180 top
R402  0E_1%  [RES0402]  192.15 128.54 180 bottom
R403  0E  [RES0402]  154.81 129.94 180 bottom
R404  0E_1%  [RES0402]  192.15 133.11 180 bottom
R405  0E_1%  [RES0402]  192.15 131.59 180 bottom
R407  0E_1%  [RES0402]  197.26 137.66 180 top
R408  22E_1%  [RES0402]  192.15 130.06 180 bottom
R409  0E_1%  [RES0402]  192.15 135.7 180 bottom
R410  0E_1%  [RES0402]  192.15 127.01 180 top
R411  0E_1%  [RES0402]  192.15 134.38 180 bottom
R412  0E_1%  [RES0402]  197.23 129.81 180 bottom
R413  0E_1%  [RES0402]  192.2 133.11 180 top
R414  0E_1%  [RES0402]  192.15 125.49 180 bottom
R415  0E_1%  [RES0402]  197.23 136.03 180 top
R416  0E_1%  [RES0402]  197.23 126.76 180 top
R417  0E_1%  [RES0402]  192.15 127.01 180 bottom
R418  0E_1%  [RES0402]  192.15 119.73 180 top
R419  0E_1%  [RES0402]  202.03 117.59 180 top
R420  0E_1%  [RES0402]  197.23 132.86 180 bottom
R421  0E_1%  [RES0402]  197.31 119.17 180 top
R422  0E_1%  [RES0402]  201.57 128.01 180 top
R423  0E_1%  [RES0402]  197.23 134.38 180 top
R424  0E_1%  [RES0402]  197.1 112.66 180 top
R425  0E_1%  [RES0402]  197.23 128.28 180 top
R426  44.2K_1%  [RES0402]  46.05 81.35 90 top
R427  0E_1%  [RES0402]  192.15 115.23 180 top
R428  0E_1%  [RES0402]  200.91 136.29 180 bottom
R429  10K_1%  [RES0402]  37.16 80.71 270 top
R430  0E_1%  [RES0402]  201.6 125.82 180 top
R431  200E_1%  [RES0402]  200.66 111.27 180 top
R432  0E_1%  [RES0402]  197.23 117.36 180 top
R433  0E_1%  [RES0402]  197.23 128.28 180 bottom
R434  0E_1%  [RES0402]  197.23 129.81 180 top
R435  0E_1%  [RES0402]  10.79 46.75 0 top
R436  0E_1%  [RES0402]  197.23 116.09 180 top
R437  0E_1%  [RES0402]  202.06 114.52 180 top
R438  10E_1%  [RES0603]  39.83 77.41 180 top
R439  0E_1%  [RES0402]  197.31 131.76 180 top
R440  0E_1%  [RES0402]  189.99 113.63 90 bottom
R441  0E_1%  [RES0402]  202.03 116.07 180 top
R442  200E_1%  [RES0402]  200.66 112.79 180 bottom
R443  10K_1%  [RES0402]  145.39 109.31 0 top
R444  0E_1%  [RES0402]  197.23 131.33 180 bottom
R445  22E_1%  [RES0402]  192.25 102.33 0 top
R446  0E_1%  [RES0402]  196.22 106.69 0 top
R447  0E_1%  [RES0402]  192.15 120.92 180 top
R448  0E_1%  [RES0402]  192.15 122.44 180 bottom
R449  22E_1%  [RES0402]  192.25 105.35 0 top
R450  0E_1%  [RES0402]  196.22 105.17 0 top
R451  0E_1%  [RES0402]  197.23 123.71 180 top
R452  0E_1%  [RES0402]  192.15 116.35 180 top
R453  22E_1%  [RES0402]  192.23 103.82 0 top
R454  0E_1%  [RES0402]  192.15 122.44 180 top
R455  10K_1%  [RES0402]  41.22 70.68 90 top
R456  0E_1%  [RES0402]  42.75 70.68 90 top
R457  0E  [RES0402]  38.94 70.55 90 top
R458  22E_1%  [RES0402]  192.15 120.92 180 bottom
R459  0E_1%  [RES0402]  197.23 120.66 180 bottom
R460  0E_1%  [RES0402]  197.23 122.19 180 top
R461  560E_1%  [RES0402]  140.21 97.93 90 top
R462  0E_1%  [RES0402]  197.23 114.06 180 top
R463  0E_1%  [RES0402]  181.38 100.57 90 top
R464  0E_1%  [RES0402]  188.85 100.6 90 top
R465  22E_1%  [RES0402]  183.77 100.73 270 top
R466  22E_1%  [RES0402]  185.29 100.73 270 top
R467  22E_1%  [RES0402]  187.07 100.73 270 top
R468  0E_1%  [RES0402]  192.15 123.97 180 top
R469  0E_1%  [RES0402]  197.23 125.24 180 bottom
R470  0E_1%  [RES0402]  192.15 123.97 180 bottom
R471  0E_1%  [RES0402]  49.47 66.47 90 top
R472  0E_1%  [RES0402]  197.26 119.12 180 bottom
R473  0E_1%  [RES0402]  192.15 125.49 180 top
R474  10K_1%  [RES0402]  136.52 98.03 90 top
R475  10K_1%  [RES0402]  138.05 98.03 270 top
R476  0E_1%  [RES0402]  197.23 126.76 180 bottom
R477  0E_1%  [RES0402]  197.23 120.66 180 top
R478  10K_1%  [RES0402]  203.58 95.52 180 top
R479  10K_1%  [RES0402]  136.02 94.76 180 top
R480  0E_1%  [RES0402]  197.23 123.71 180 bottom
R481  0E_1%  [RES0402]  197.23 122.19 180 bottom
R482  0E_1%  [RES0402]  197.23 125.24 180 top
R483  10K_1%  [RES0402]  137.16 92.98 180 top
R485  10K_1%  [RES0402]  135.76 91.33 0 top
R486  1K  [RES0402]  117.22 91.98 180 top
R487  10K_1%  [RES0402]  119.63 91.33 270 top
R488  0E_1%  [RES0402]  154.18 86.63 0 top
R489  0E_1%  [RES0402]  154.18 88.19 0 top
R490  10K_1%  [RES0402]  193.22 147.46 270 top
R491  10K_1%  [RES0402]  195.12 147.46 270 top
R492  10K_1%  [RES0402]  196.72 155.46 0 bottom
R493  0E_1%  [RES0402]  137.03 84.72 90 top
R494  4.7K_5%  [RES0402]  89.69 116.12 90 bottom
R495  2K_1%  [RES0402]  136.27 82.44 0 top
R496  0E_1%  [RES0402]  135.51 84.72 90 top
R497  4.7K_5%  [RES0402]  91.21 116.12 270 top
R498  10K_1%  [RES0402]  177.67 90.57 0 top
R499  10K_1%  [RES0402]  178.94 87.14 270 top
R500  0E_1%  [RES0402]  278.84 50.18 270 top
R501  10K_1%  [RES0402]  168.02 85.36 0 bottom
R502  10K_1%  [RES0402]  196.72 156.99 0 bottom
R503  10K_1%  [RES0402]  292.79 48.36 90 top
R504  4.7K_5%  [RES0402]  20.57 56.3 90 top
R507  22E_1%  [RES0402]  128.57 69.61 90 top
R508  22E_1%  [RES0402]  130.1 69.61 90 top
R509  22E_1%  [RES0402]  131.62 69.61 90 top
R510  22E_1%  [RES0402]  133.15 69.61 90 top
R511  0E_1%  [RES0402]  160.91 95.98 90 top
R512  0E_1%  [RES0402]  162.56 95.98 90 top
R513  0E_1%  [RES0402]  164.08 95.98 90 top
R514  0E_1%  [RES0402]  159.38 95.98 90 top
R515  100E_5%  [RES0402]  5.33 50.94 180 top
R517  0E_1%  [RES0402]  122.48 64.28 0 top
R518  0E  [RES0402]  201.04 69.61 0 top
R520  10K_1%  [RES0402]  143.74 51.38 180 top
R521  0E_1%  [RES0402]  143.74 51.38 180 bottom
R522  0E_1%  [RES0402]  122.48 62.12 180 top
R523  1K  [RES0402]  142.85 53.92 90 top
R526  0E  [RES0402]  110.87 114.19 0 bottom
R527  0E  [RES0402]  182.52 53.56 270 top
R528  1K  [RES0402]  179.76 50.56 270 top
R529  0E_1%  [RES0402]  179.25 41.16 90 top
R530  1K  [RES0402]  178.99 48.15 0 top
R531  10K_1%  [RES0402]  176.33 63.51 90 top
R532  22E_1%  [RES0402]  176.33 58.69 270 top
R533  10K_1%  [RES0402]  174.8 63.51 90 top
R534  10K_1%  [RES0402]  273.3 47.39 270 top
R535  10K_1%  [RES0402]  274.83 47.39 270 top
R536  0E  [RES0402]  281.81 47.39 180 top
R537  0E_1%  [RES0402]  278.38 47 270 top
R538  22E_1%  [RES0402]  174.8 58.69 270 top
R539  33E  [RES0402]  154.53 101.74 90 bottom
R540  33E  [RES0402]  39.98 160.34 180 top
R541  10K_1%  [RES0402]  173.28 63.51 90 top
R542  0E_1%  [RES0402]  27.49 129.61 0 top
R543  0E  [RES0402]  281.81 45.73 180 top
R544  33E  [RES0402]  161.82 99.89 180 bottom
R545  33E  [RES0402]  35.05 195.8 180 top
R546  22E_1%  [RES0402]  173.28 58.69 270 top
R547  0E_1%  [RES0402]  27.49 128.08 180 top
R548  10K_1%  [RES0402]  171.75 63.51 90 top
R549  22E_1%  [RES0402]  171.75 58.69 270 top
R550  4.7K_5%  [RES0402]  292.74 31.38 90 top
R552  1K  [RES0402]  170.23 63.51 90 top
R553  0E_1%  [RES0402]  292.99 43.07 90 top
R554  22E_1%  [RES0402]  170.23 58.69 270 top
R555  0E  [RES0402]  107.04 25.31 90 top
R556  10K_1%  [RES0402]  97.74 46.6 270 top
R557  4.7K_5%  [RES0402]  294.26 31.38 90 top
R558  0E_1%  [RES0402]  294.51 43.07 90 top
R559  1K  [RES0402]  168.71 63.51 90 top
R560  22E_1%  [RES0402]  168.71 58.69 270 top
R561  0E_1%  [RES0402]  99.39 51.04 0 top
R562  2.2K_1%  [RES0402]  99.64 46.6 270 top
R563  0E_1%  [RES0402]  296.67 40.02 270 top
R564  0E_1%  [RES0402]  296.67 43.19 270 top
R565  4.7K_5%  [RES0402]  165.28 58.18 0 top
R566  100K_1%  [RES0402]  165.4 53.48 0 top
R567  12.1K_1%  [RES0603]  167.69 46.5 270 top
R568  0E  [RES0402]  102.31 54.35 0 top
R570  10K_1%  [RES0402]  160.32 53.35 0 top
R571  10K_1%  [RES0402]  133.02 25.69 270 top
R572  10K_1%  [RES0402]  134.54 25.69 270 top
R573  10K_1%  [RES0402]  136.07 25.69 270 top
R574  10K_1%  [RES0402]  137.59 25.69 270 top
R575  10K_1%  [RES0402]  139.12 25.69 270 top
R576  10K_1%  [RES0402]  140.64 25.69 270 top
R577  10K_1%  [RES0402]  231.7 26.38 90 top
R578  0E_1%  [RES0402]  125.17 21.83 90 top
R579  0E_1%  [RES0402]  126.7 21.83 90 top
R580  120E_1%  [RES0402]  15.34 159.32 90 top
R581  120E_1%  [RES0402]  14.99 201.87 90 top
R582  0.0E  [RES0603]  10.26 217.82 90 bottom
R583  0.0E  [RES0603]  10.24 175.91 90 bottom
R584  10K_1%  [RES0402]  199.01 13.86 180 top
R585  220E_1%  [RES0402]  183.77 23.51 0 bottom
R586  220E_1%  [RES0402]  154.81 16.91 0 bottom
R588  50E  [RES0402]  57.68 138.61 90 bottom
R589  50E  [RES0402]  61.75 138.36 90 bottom
R590  0E_1%  [RES0402]  163.7 247.92 90 bottom
R591  50E  [RES0402]  28.96 247.16 90 bottom
R592  100E_5%  [RES0402]  24.38 247.03 90 bottom
R593  0E_1%  [RES0402]  194.94 247.54 90 bottom
R594  10K_1%  [RES0402]  216.28 240.04 180 bottom
R595  0E_1%  [RES0402]  205.61 222.01 0 top
R596  0E_1%  [RES0402]  205.61 220.49 0 top
R597  150K_1%  [RES0402]  258.09 17.92 90 bottom
R598  10K_1%  [RES0402]  216.28 235.98 180 bottom
R599  24.3K_1%  [RES0402]  288.77 105.78 180 bottom
R600  12.1K_1%  [RES0603]  288.52 104.13 0 bottom
R601  10K_1%  [RES0402]  28.07 238.52 90 bottom
R602  0E_1%  [RES0402]  23.37 238.52 270 bottom
R603  0E  [RES0402]  285.6 91.94 0 bottom
R604  10K_1%  [RES0402]  205.74 232.04 180 top
R605  0E_1%  [RES0402]  182.88 236.23 270 bottom
R606  0E_1%  [RES0402]  216.28 230.01 180 bottom
R607  1.58K_1%  [RES0402]  129.92 231.79 0 bottom
R608  0E  [RES0402]  280.01 92.06 270 bottom
R609  0E  [RES0402]  198.25 232.42 180 bottom
R610  150K_1%  [RES0402]  131.06 225.31 180 bottom
R611  10K_1%  [RES0402]  276.45 93.46 180 bottom
R612  10K_1%  [RES0402]  255.4 96.41 0 bottom
R613  10K_1%  [RES0402]  250.55 66.11 270 bottom
R614  10K_1%  [RES0402]  249.02 66.11 270 bottom
R615  10K_1%  [RES0402]  247.5 66.11 270 bottom
R616  22E_1%  [RES0402]  245.97 66.11 270 bottom
R617  10K_1%  [RES0402]  244.45 66.11 270 bottom
R618  22E_1%  [RES0402]  242.32 66.11 270 top
R619  22E_1%  [RES0402]  239.14 66.11 270 bottom
R620  22E_1%  [RES0402]  237.74 66.11 270 top
R621  2.2K_1%  [RES0402]  234.16 65.34 270 bottom
R622  2.2K_1%  [RES0402]  235.69 65.34 270 bottom
R623  2.2K_1%  [RES0402]  232.64 65.34 270 bottom
R624  2.2K_1%  [RES0402]  231.11 65.34 270 bottom
R625  10K_1%  [RES0402]  28.07 232.81 270 bottom
R626  2.2K_1%  [RES0402]  259.31 62.04 0 bottom
R630  0E_1%  [RES0402]  259.82 56.58 0 bottom
R633  10K_1%  [RES0402]  260.86 224.93 180 top
R635  0E_1%  [RES0402]  254.86 52.26 0 bottom
R636  4.7K_5%  [RES0402]  252.32 53.41 0 bottom
R637  10K_1%  [RES0402]  196.85 222.75 180 top
R638  10K_1%  [RES0402]  189.84 218.76 270 top
R639  22E_1%  [RES0402]  99.06 204.48 0 bottom
R640  10K_1%  [RES0402]  263.25 50.61 0 bottom
R641  4.7K_5%  [RES0402]  268.5 73.62 270 bottom
R642  1K  [RES0402]  226.92 49.98 0 bottom
R643  10K_1%  [RES0402]  232.41 96.79 180 bottom
R644  10K_1%  [RES0402]  226.92 46.93 180 bottom
R645  4.7K_5%  [RES0402]  82.17 205.12 90 bottom
R646  4.7K_5%  [RES0402]  80.65 205.12 90 bottom
R647  10K_1%  [RES0402]  264.8 218.33 90 bottom
R649  10K_1%  [RES0402]  226.92 48.58 180 bottom
R650  10K_1%  [RES0402]  263.25 44.52 0 top
R651  1K  [RES0402]  226.92 45.28 0 bottom
R652  0E  [RES0402]  92.46 200.93 270 bottom
R653  1K  [RES0402]  226.92 43.5 0 bottom
R654  1K  [RES0402]  226.92 41.98 0 bottom
R655  10K_1%  [RES0402]  85.73 200.42 270 bottom
R657  1K  [RES0402]  230.86 39.94 90 bottom
R658  1K  [RES0402]  232.38 39.94 90 bottom
R659  10K_1%  [RES0402]  88.52 196.23 0 bottom
R660  10K_1%  [RES0402]  88.52 194.71 0 bottom
R661  4.7K_5%  [RES0402]  83.44 191.4 0 bottom
R662  10K_1%  [RES0402]  88.52 193.18 0 bottom
R663  4.7K_5%  [RES0402]  83.44 192.52 0 top
R664  10K_1%  [RES0402]  88.52 191.66 0 bottom
R665  10K_1%  [RES0402]  89.66 187.97 90 bottom
R666  0E_1%  [RES0402]  68.2 186.7 180 bottom
R667  0E_1%  [RES0402]  68.2 188.23 180 top
R668  10K_1%  [RES0402]  239.14 185.56 270 bottom
R670  0E_1%  [RES0402]  248.03 180.02 90 bottom
R671  0E_1%  [RES0402]  246.38 180.02 90 bottom
R672  10K_1%  [RES0402]  85.73 179.59 0 bottom
R673  0E_1%  [RES0402]  174.11 175.47 270 bottom
R674  0E_1%  [RES0402]  228.9 177.36 0 bottom
R675  10K_1%  [RES0402]  64.39 177.94 90 bottom
R676  0E_1%  [RES0402]  175.25 198.84 270 bottom
R677  10K_1%  [RES0402]  49.91 180.48 0 bottom
R678  47E_1%  [RES0402]  175.12 194.77 270 bottom
R679  0E_1%  [RES0402]  175.25 171.28 270 bottom
R680  0E_1%  [RES0402]  175.63 175.47 270 bottom
R681  47E_1%  [RES0402]  176.65 194.77 270 bottom
R682  0E_1%  [RES0402]  176.9 171.28 270 bottom
R683  10K_1%  [RES0402]  68.96 175.4 0 bottom
R684  10K_1%  [RES0402]  43.31 178.2 0 bottom
R685  0E_1%  [RES0402]  182.62 175.47 270 bottom
R686  10K_1%  [RES0402]  77.72 174.77 0 bottom
R687  47E_1%  [RES0402]  178.43 194.77 270 bottom
R688  0E_1%  [RES0402]  178.81 171.28 270 bottom
R689  10K_1%  [RES0402]  68.96 173.75 0 bottom
R690  10K_1%  [RES0402]  43.31 176.67 0 bottom
R691  0E_1%  [RES0402]  179.19 175.47 270 bottom
R692  0E_1%  [RES0402]  251.74 170.27 180 bottom
R693  240E_1%  [RES0402]  137.54 172.86 90 bottom
R694  10K_1%  [RES0402]  178.93 198.46 90 bottom
R695  0E_1%  [RES0402]  180.97 175.47 270 bottom
R696  10K_1%  [RES0402]  58.42 169.56 0 bottom
R697  10K_1%  [RES0402]  225.5 81.22 0 bottom
R698  10K_1%  [RES0402]  207.32 168.94 180 top
R699  10K_1%  [RES0402]  88.01 165.62 90 bottom
R700  0E_1%  [RES0402]  195.51 170.21 180 bottom
R701  10K_1%  [RES0402]  207.32 171.99 0 top
R702  10K_1%  [RES0402]  240.79 162.7 90 bottom
R703  0E_1%  [RES0402]  232.54 160.42 180 bottom
R704  240E_1%  [RES0402]  137.29 157.49 90 bottom
R705  4.7K_5%  [RES0402]  165.99 149.62 90 bottom
R706  4.7K_5%  [RES0402]  164.47 149.62 90 bottom
R707  0E_1%  [RES0402]  169.8 148.73 270 bottom
R708  0E_1%  [RES0402]  168.02 148.73 270 bottom
R709  4.7K_5%  [RES0402]  271.65 146.06 270 bottom
R710  0E_1%  [RES0402]  163.7 144.41 270 bottom
R711  0E_1%  [RES0402]  162.18 144.41 270 bottom
R712  240E_1%  [RES0402]  137.29 141.75 90 bottom
R713  0E_1%  [RES0402]  180.47 139.21 270 bottom
R714  0E_1%  [RES0402]  178.94 139.21 270 bottom
R715  0E_1%  [RES0402]  175.89 139.21 270 bottom
R716  0E_1%  [RES0402]  169.8 139.21 270 bottom
R717  10K_1%  [RES0402]  212.22 90.18 180 bottom
R718  240E_1%  [RES0402]  137.03 126.63 90 bottom
R719  3.00K_1%  [RES0201]  177.24 124.96 135 bottom
R720  0E_1%  [RES0402]  198.12 116.35 90 bottom
R721  10E  [RES0402]  42.54 81.04 90 top
R722  240E_1%  [RES0402]  137.03 110.12 90 bottom
R723  10K_1%  [RES0402]  145.41 109.23 180 bottom
R724  0E_1%  [RES0402]  152.65 106.87 270 bottom
R725  0E_1%  [RES0402]  41.22 70.68 90 bottom
R726  10K_1%  [RES0402]  218.82 51.2 0 bottom
R727  10K_1%  [RES0402]  214.38 51.2 180 bottom
R728  0E_1%  [RES0402]  49.48 66.49 270 bottom
R729  10K_1%  [RES0402]  69.38 55.69 0 bottom
R730  10K_1%  [RES0402]  203.58 95.52 0 bottom
R731  10K_1%  [RES0402]  136.02 94.76 0 bottom
R732  50E  [RES0402]  154.43 93.23 180 bottom
R733  10K_1%  [RES0402]  137.16 92.98 0 bottom
R734  50E  [RES0402]  154.43 91.71 180 bottom
R735  10K_1%  [RES0402]  198.3 24.2 180 bottom
R736  10K_1%  [RES0402]  193.73 24.2 180 bottom
R737  10K_1%  [RES0402]  176.28 138.95 270 top
R738  10K_1%  [RES0402]  135.76 91.33 180 bottom
R740  33E  [RES0402]  198.75 82.69 180 top
R741  10K_1%  [RES0402]  178.94 87.14 90 bottom
R742  10K_1%  [RES0402]  276.25 57.19 0 top
R743  10K_1%  [RES0402]  193.67 79.64 90 bottom
R744  10K_1%  [RES0402]  176.4 88.28 270 bottom
R745  10K_1%  [RES0402]  193.67 73.42 270 bottom
R746  10K_1%  [RES0402]  202.56 71.39 0 bottom
R747  10K_1%  [RES0402]  45.59 110.63 270 bottom
R748  100E_5%  [RES0402]  152.81 247.74 0 bottom
